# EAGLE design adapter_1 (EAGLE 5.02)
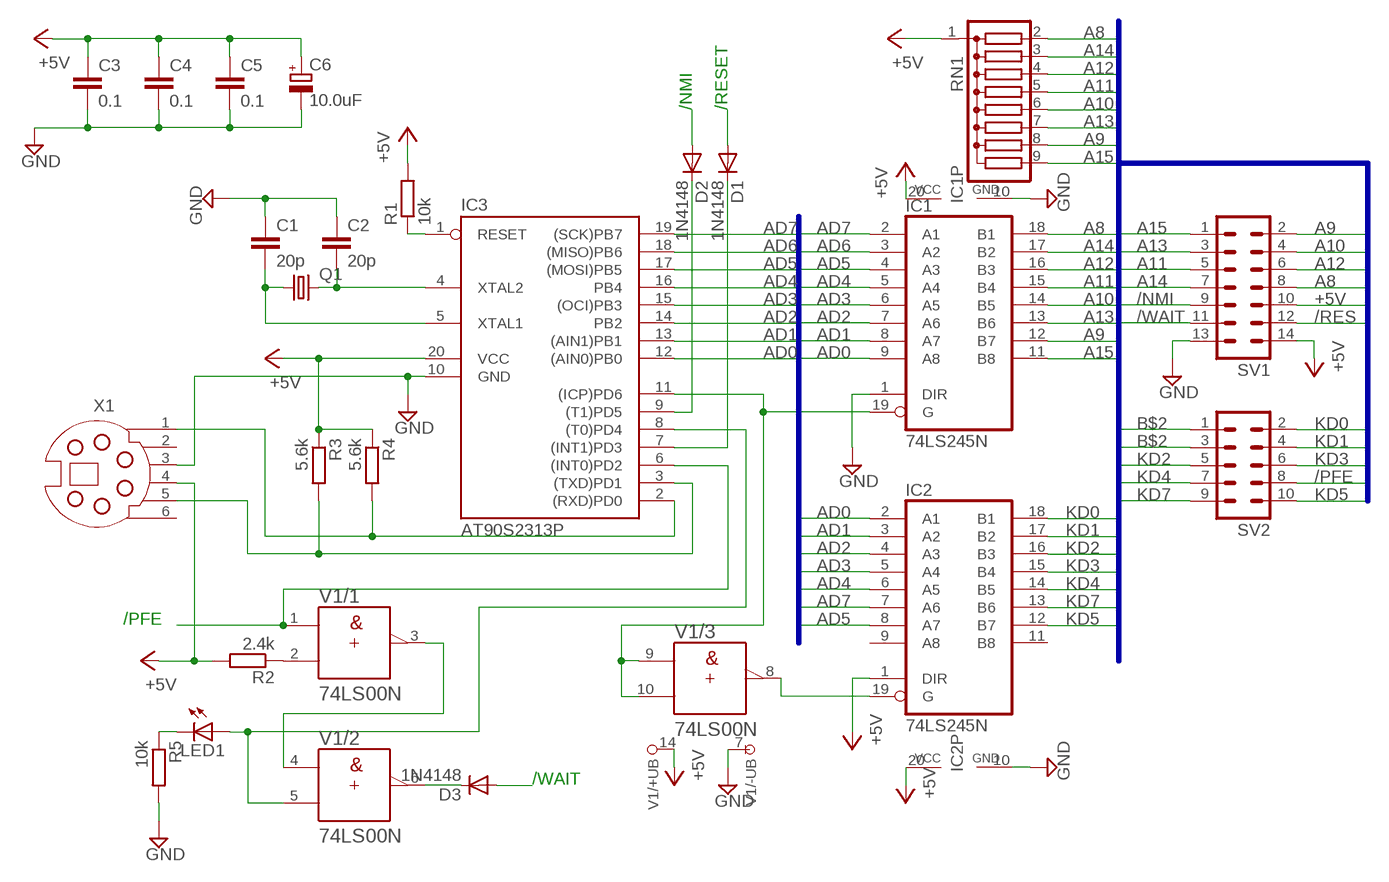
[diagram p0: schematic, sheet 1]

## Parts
C1  20p  C-EU050-024X044  [C050-024X044]
C2  20p  C-EU050-024X044  [C050-024X044]
C3  0.1  C-EU075-032X103  [C075-032X103]
C4  0.1  C-EU050-024X044  [C050-024X044]
C5  0.1  C-EU050-024X044  [C050-024X044]
C6  10.0uF  CPOL-EUE2-4  [E2-4]
D1  1N4148  [DO35-10]
D2  1N4148  [DO35-10]
D3  1N4148  [DO35-10]
IC1  74LS245N  [DIL20]
IC2  74LS245N  [DIL20]
IC3  AT90S2313P  [DIL20]
LED1  LED3MM  [LED3MM]
Q1  CRYSTALHC49U-V  [HC49U-V]
R1  10k  R-EU_0204/7  [0204/7]
R2  2.4k  R-EU_0204/7  [0204/7]
R3  5.6k  R-EU_0204/2V  [0204V]
R4  5.6k  R-EU_0204/2V  [0204V]
R5  10k  R-EU_0204/2V  [0204V]
RN1  G08R  [SIL9]
SV1  ML14  [ML14]
SV2  ML10  [ML10]
V1  74LS00N  [DIL14]
X1  SSV-G06  [SSV-BC06]

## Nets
+5V: C3.1 C4.1 C5.1 C6.+ IC1.20(VCC) IC2.1(DIR) IC2.20(VCC) IC3.20(VCC) R1.2 R2.2 R3.1 R4.1 RN1.1 SV1.10 SV1.14 V1.14(/+UB:+UB) X1.4
/NMI: D2.A SV1.9
/PFE: IC3.6((INT0)PD2) SV2.8 V1.1(/1:A)
/RES: D1.A SV1.12
/WAIT: D3.A SV1.11
A8: IC1.18(B1) RN1.2 SV1.8
A9: IC1.12(B7) RN1.8 SV1.2
A10: IC1.14(B5) RN1.6 SV1.4
A11: IC1.15(B4) RN1.5 SV1.5
A12: IC1.16(B3) RN1.4 SV1.6
A13: IC1.13(B6) RN1.7 SV1.3
A14: IC1.17(B2) RN1.3 SV1.7
A15: IC1.11(B8) RN1.9 SV1.1
AD0: IC1.9(A8) IC2.2(A1) IC3.12((AIN0)PB0)
AD1: IC1.8(A7) IC2.3(A2) IC3.13((AIN1)PB1)
AD2: IC1.7(A6) IC2.4(A3) IC3.14(PB2)
AD3: IC1.6(A5) IC2.5(A4) IC3.15((OCI)PB3)
AD4: IC1.5(A4) IC2.6(A5) IC3.16(PB4)
AD5: IC1.4(A3) IC2.8(A7) IC3.17((MOSI)PB5)
AD6: IC1.3(A2) IC3.18((MISO)PB6)
AD7: IC1.2(A1) IC2.7(A6) IC3.19((SCK)PB7)
B$2: SV2.1 SV2.3
GND: C1.1 C2.1 C3.2 C4.2 C5.2 C6.- IC1.1(DIR) IC1.10(GND) IC2.10(GND) IC3.10(GND) R5.2 SV1.13 V1.7(/-UB:-UB) X1.3
KD0: IC2.18(B1) SV2.2
KD1: IC2.17(B2) SV2.4
KD2: IC2.16(B3) SV2.5
KD3: IC2.15(B4) SV2.6
KD4: IC2.14(B5) SV2.7
KD5: IC2.12(B7) SV2.10
KD7: IC2.13(B6) SV2.9
N$1: IC3.1(RESET) R1.1
N$2: V1.3(/1:Y) V1.4(/2:A)
N$3: C2.2 IC3.4(XTAL2) Q1.2
N$4: C1.2 IC3.5(XTAL1) Q1.1
N$5: IC3.8((T0)PD4) LED1.A V1.5(/2:B)
N$6: IC1.19(G) IC3.11((ICP)PD6) V1.9(/3:A) V1.10(/3:B)
N$7: R2.1 V1.2(/1:B)
N$8: IC2.19(G) V1.8(/3:Y)
N$9: IC3.2((RXD)PD0) R4.2 X1.1
N$10: IC3.3((TXD)PD1) R3.2 X1.5
N$11: LED1.K(C) R5.1
N$13: D2.C IC3.9((T1)PD5)
N$14: D1.C IC3.7((INT1)PD3)
N$17: D3.C V1.6(/2:Y)
Unconnected: IC2.9(A8) IC2.11(B8) V1.11(/4:Y) V1.12(/4:A) V1.13(/4:B) X1.2 X1.6

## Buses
B$1
B$2

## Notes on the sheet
- /NMI | /RESET
- /PFE
- /WAIT

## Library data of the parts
C1-C5 = rcl:C-EU: CAPACITOR, European symbol
C6 = rcl:CPOL-EU: POLARIZED CAPACITOR, European symbol
D1-D3 = diode:1N4148: DIODE
IC1 IC2 = 74xx-eu:74*245: Octal BUS TRANSCEIVER, 3-state
IC3 = atmel:AT90S2313: MICROCONTROLLER 2 Kbytes FLASH 128 bytes SRAM 128 bytes EEPROM UART
LED1 = led:LED: LED
Q1 = crystal:CRYSTAL: CRYSTAL
R1-R5 = rcl:R-EU_: RESISTOR, European symbol
RN1 = resistor-sil:G08R: SIL RESISTOR
SV1 = con-ml:ML14: HARTING
SV2 = con-ml:ML10: HARTING
V1 = 74ttl-din:74*00: Quad 2-input NAND gate
X1 = con-yamaichi:SSV-G06: YAMAICHI CONNECTOR

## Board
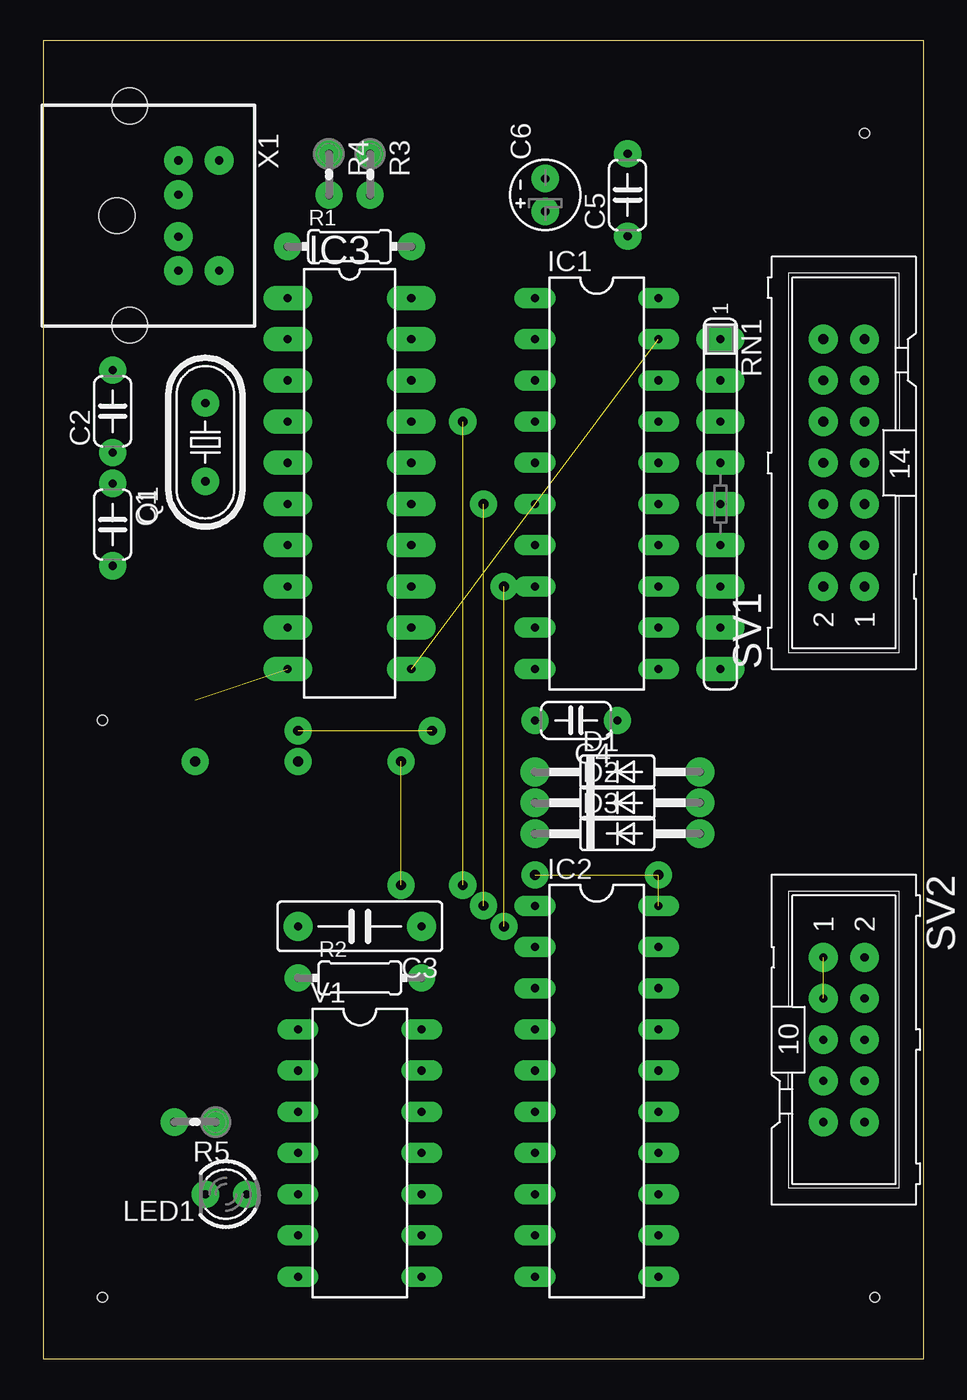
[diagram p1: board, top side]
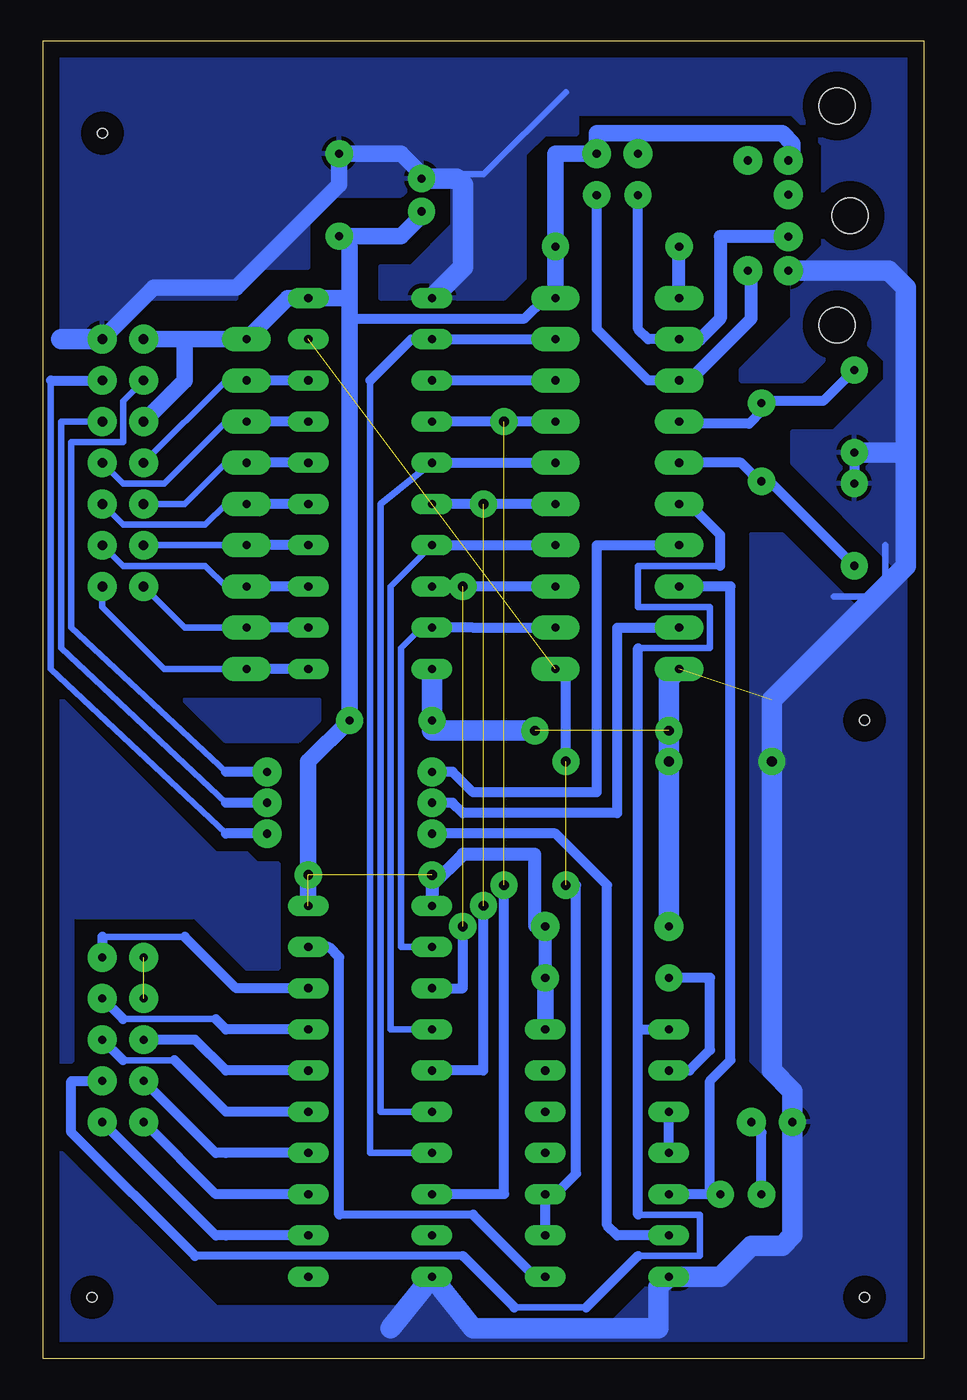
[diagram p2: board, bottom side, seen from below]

Size 54.28 x 81.27 mm. Coordinates in mm from the lower left corner, seen from the top.
Outline: 0,0 54.28,0 54.28,81.27 0,81.27 0,0
Copper layers (1*16): Top 0.035mm / dielectric 1.5mm / Bottom 0.035mm
Design rules "default": minimum track width 10mil, minimum drill 24mil, track to track 8mil, track to pad 8mil, pad to pad 8mil, via to via 8mil, smd to smd 8mil, copper to edge 40mil, drill to drill 8mil, minimum pad ring 10mil, minimum via ring 8mil, stop-mask expansion 4mil, vias tented up to drill 0mil, thermal gap 10mil
Holes 0.6 mm at 50.63,75.56 3.64,3.8 3.64,39.37 51.27,3.8

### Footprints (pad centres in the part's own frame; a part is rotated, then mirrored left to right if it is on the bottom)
C050-024X044 = drill 0.5 pad 1.676 round: 1 -2.54,0; 2 2.54,0
C075-032X103 = drill 0.5 pad 1.778 round: 1 -3.81,0; 2 3.81,0
E2-4 = drill 0.5 pad 1.676 round: + -1.016,0; - 1.016,0
DO35-10 = drill 0.5 pad 1.778 round: A 5.08,0; C -5.08,0
DIL20 = drill 0.5 pad 1.27 long: 1 -11.43,-3.81; 2 -8.89,-3.81; 3 -6.35,-3.81; 4 -3.81,-3.81; 5 -1.27,-3.81; 6 1.27,-3.81; 7 3.81,-3.81; 8 6.35,-3.81; 9 8.89,-3.81; 10 11.43,-3.81; 11 11.43,3.81; 12 8.89,3.81; 13 6.35,3.81; 14 3.81,3.81; 15 1.27,3.81; 16 -1.27,3.81; 17 -3.81,3.81; 18 -6.35,3.81; 19 -8.89,3.81; 20 -11.43,3.81
DIL20' = drill 0.5 pad 1.5 long: 1 -11.43,-3.81; 2 -8.89,-3.81; 3 -6.35,-3.81; 4 -3.81,-3.81; 5 -1.27,-3.81; 6 1.27,-3.81; 7 3.81,-3.81; 8 6.35,-3.81; 9 8.89,-3.81; 10 11.43,-3.81; 11 11.43,3.81; 12 8.89,3.81; 13 6.35,3.81; 14 3.81,3.81; 15 1.27,3.81; 16 -1.27,3.81; 17 -3.81,3.81; 18 -6.35,3.81; 19 -8.89,3.81; 20 -11.43,3.81
LED3MM = drill 0.5 pad 1.676 round: A -1.27,0; K 1.27,0
HC49U-V = drill 0.5 pad 1.676 round: 1 -2.413,0; 2 2.413,0
0204/7 = drill 0.5 pad 1.676 round: 1 -3.81,0; 2 3.81,0
0204V = drill 0.5 pad 1.778 round: 1 -1.27,0 | drill 0.5 pad 1.676 round: 2 1.27,0
SIL9 = drill 0.5 pad 1.5 long: 1 -10.16,0; 2 -7.62,0; 3 -5.08,0; 4 -2.54,0; 5 0,0; 6 2.54,0; 7 5.08,0; 8 7.62,0; 9 10.16,0
ML14 = drill 0.6 pad 1.778 round: 1 -7.62,-1.27; 2 -7.62,1.27; 3 -5.08,-1.27; 4 -5.08,1.27; 5 -2.54,-1.27; 6 -2.54,1.27; 7 0,-1.27; 8 0,1.27; 9 2.54,-1.27; 10 2.54,1.27; 11 5.08,-1.27; 12 5.08,1.27; 13 7.62,-1.27; 14 7.62,1.27
ML10 = drill 0.5 pad 1.778 round: 1 -5.08,-1.27; 2 -5.08,1.27; 3 -2.54,-1.27; 4 -2.54,1.27; 5 0,-1.27; 6 0,1.27; 7 2.54,-1.27; 8 2.54,1.27; 9 5.08,-1.27; 10 5.08,1.27
DIL14 = drill 0.5 pad 1.27 long: 1 -7.62,-3.81; 2 -5.08,-3.81; 3 -2.54,-3.81; 4 0,-3.81; 5 2.54,-3.81; 6 5.08,-3.81; 7 7.62,-3.81; 8 7.62,3.81; 9 5.08,3.81; 10 2.54,3.81; 11 0,3.81; 12 -2.54,3.81; 13 -5.08,3.81; 14 -7.62,3.81
SSV-BC06 = drill 0.5 pad 1.778 round: 1 1.3,8.5; 2 -1.3,8.5; 3 3.4,8.5; 4 -3.4,8.5; 5 3.4,11; 6 -3.4,11 | hole 2.2: -6.75,5.5; 0,4.7; 6.75,5.5

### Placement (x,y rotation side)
C1  4.28,51.43 270 top
C2  4.28,58.41 90 top
C3  19.52,26.66 180 top
C4  32.85,39.37 180 top
C5  36.03,71.75 90 top
C6  30.95,71.75 90 top
D1  35.39,36.19 0 top
D2  35.39,34.29 0 top
D3  35.39,32.38 0 top
IC1  34.12,53.97 270 top
IC2  34.12,16.5 270 top
IC3  AT90S2313P  [DIL20']  18.88,53.97 270 top
LED1  11.27,10.16 180 top
Q1  10,56.51 90 top
R1  18.88,68.57 0 top
R2  19.52,23.49 0 top
R3  20.15,73.02 270 top
R4  17.61,73.02 270 top
R5  9.36,14.6 180 top
RN1  41.74,52.7 270 top
SV1  49.37,55.24 90 top
SV2  49.37,19.68 270 top
V1  19.52,12.7 270 top
X1  -0.17,70.48 270 top

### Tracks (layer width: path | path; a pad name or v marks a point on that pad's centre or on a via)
+5V  (via drill 0.6 pad 1.68)  (2 unrouted)
  Bottom 0.61: IC3.20 23.33,65.4 24.6,64.13 35.39,64.13
  Bottom 0.813: V1.14 C3.1 23.96,26.66 23.96,31.11 28.41,31.11 30.31,29.2 | 30.31,29.2 IC2.1 | 30.31,29.2 v30.31,29.84
  Bottom 1.016: 45.55,62.86 RN1.1 39.2,65.4 IC1.20 35.39,65.4 | 45.55,62.86 SV1.14 | SV1.10 45.55,60.32 45.55,62.86 | IC2.20 37.94,36.83 C4.1 35.39,64.13 35.39,65.4 | IC3.20 R1.2 22.7,74.29 R3.1 20.15,75.56 17.61,75.56 | X1.4 8.31,73.88 8.09,73.66 8.09,74.92 8.73,75.56 17.61,75.56 | 17.61,75.56 R4.1 | V1.14 R2.2 | 35.39,65.4 35.39,68.57 C5.1 32.22,69.21 30.95,70.48 C6.+
  other vias: 37.94,29.84
/NMI
  Bottom 0.406: 43.02,34.29 53.17,43.81 53.17,57.78 SV1.9
  Bottom 0.61: D2.A 43.02,34.29
/PFE
  Bottom 0.406: 20.79,3.17 25.23,3.17 | 17.61,43.81 13.17,43.81 13.17,46.35 17.61,46.35 17.61,48.89 12.54,48.89 | 17.61,8.89 13.81,8.89 13.81,6.34 17.61,6.34
  Bottom 0.5: 28.41,6.34 44.92,6.34
  Bottom 0.61: 25.23,3.17 28.41,6.34 | IC3.6 14.44,52.7 12.54,50.8 12.54,48.89 | 17.61,20.31 17.61,43.81 | 17.61,20.31 V1.1 | 17.61,8.89 17.61,20.31 | 17.61,6.34 20.79,3.17 | 44.92,6.34 52.54,13.97 52.54,17.14 SV2.8
/RES
  Bottom 0.406: 43.02,36.19 52.54,45.08 52.54,56.51 49.37,56.51 49.37,59.05 SV1.12
  Bottom 0.61: D1.A 43.02,36.19
/WAIT
  Bottom 0.406: 43.02,32.38 53.81,42.54 53.81,60.32
  Bottom 0.61: D3.A 43.02,32.38 | 53.81,60.32 SV1.11
A8
  Bottom 0.406: SV1.8 43.02,60.32 RN1.2
  Bottom 0.61: IC1.18 RN1.2
A9
  Bottom 0.406: RN1.8 45.55,45.08 SV1.2
  Bottom 0.61: IC1.12 RN1.8
A10
  Bottom 0.406: RN1.6 SV1.4
  Bottom 0.61: IC1.14 RN1.6
A11
  Bottom 0.406: SV1.5 49.37,51.43 44.28,51.43 43.02,52.7 RN1.5
  Bottom 0.61: IC1.15 RN1.5
A12
  Bottom 0.406: SV1.6 45.55,52.7 43.02,55.24 RN1.4
  Bottom 0.61: IC1.16 RN1.4
A13
  Bottom 0.406: SV1.3 49.37,48.89 44.28,48.89 43.02,47.62 RN1.7
  Bottom 0.61: IC1.13 RN1.7
A14
  Bottom 0.406: SV1.7 49.37,53.97 46.82,53.97 43.02,57.78 RN1.3
  Bottom 0.61: IC1.17 RN1.3
A15
  Bottom 0.406: RN1.9 46.82,42.54 50.63,46.35 SV1.1
  Bottom 0.61: IC1.11 RN1.9
AD0
  Bottom 0.406: 27.77,45.08 30.95,45.08 32.22,43.81 32.22,25.39 IC2.2
  Bottom 0.61: IC3.12 27.77,45.08 IC1.9
AD1  (via drill 0.6 pad 1.68)  (1 unrouted)
  Bottom 0.61: IC3.13 v28.41,47.62 IC1.8 | v28.41,26.66 28.41,22.86 IC2.3
AD2
  Bottom 0.406: IC1.7 32.85,47.62 32.85,20.31 IC2.4
  Bottom 0.61: IC1.7 IC3.14
AD3  (via drill 0.6 pad 1.68)  (1 unrouted)
  Bottom 0.61: IC3.15 v27.14,52.7 IC1.6 | IC2.5 27.14,17.77 v27.14,27.93
AD4
  Bottom 0.406: IC2.6 33.49,15.24 33.49,52.7 IC1.5
  Bottom 0.61: IC1.5 IC3.16
AD5  (via drill 0.6 pad 1.68)  (1 unrouted)
  Bottom 0.61: IC3.17 v25.87,57.78 IC1.4 | IC2.8 25.87,10.16 v25.87,29.2
AD6
  Bottom 0.61: IC3.18 IC1.3
AD7
  Bottom 0.406: 34.12,60.32 34.12,12.7 IC2.7
  Bottom 0.61: IC3.19 IC1.2 31.58,62.86 34.12,60.32
B$2  (1 unrouted)
GND  (via drill 0.6 pad 1.68)  (2 unrouted)
  Bottom 0.406: 30.95,73.02 27.14,73.02 22.06,78.1 | 5.55,46.98 2.38,46.98 2.38,50.16
  Bottom 0.61: C2.1 C1.1
  Bottom 1.016: C6.- 30.95,73.02 32.22,74.29 C5.2 36.03,72.38 42.38,66.03 47.46,66.03 SV1.13
  Bottom 1.27: C3.2 v15.71,36.83 v15.71,38.73 15.71,41.91 IC3.10 | C4.2 IC1.10 30.31,38.73 v23.96,38.73 | C6.- 28.79,72.77 28.41,72.38 28.41,67.3 IC1.1 | X1.3 2.15,67.08 1.1,66.03 1.1,55.88 | 1.1,55.88 C2.1 | 9.36,40.64 v9.36,36.83 | 9.36,40.64 1.1,48.89 1.1,55.88 | 9.36,40.64 9.36,17.77 8.09,16.5 R5.2 8.09,7.62 8.73,6.98 10.63,6.98 12.54,5.08 V1.7 16.34,4.44 16.34,1.9 27.77,1.9 IC2.10 32.85,1.9 | SV1.13 53.17,62.86
  pour Bottom: 8.09,16.5 0.47,16.5 0.47,-0.01 54.45,-0.01 54.45,30.47 39.84,30.47 39.84,24.12 41.74,24.12 44.92,27.3 52.54,27.3 52.54,18.41 53.81,18.41 53.81,13.33 43.65,3.17 32.22,3.17 30.31,5.08 27.14,1.9 19.52,1.9 16.34,5.08 13.17,5.08 12.54,5.71 11.9,5.71 10.63,6.98 8.73,6.98 8.09,7.62
  pour Bottom: 54.45,62.86 50.63,62.86 48.09,65.4 42.38,65.4 42.38,66.67 41.74,66.67 41.11,67.3 37.94,67.3 37.94,70.48 36.66,71.75 32.22,71.75 31.58,72.38 29.04,72.38 29.04,69.84 31.58,67.3 33.49,67.3 33.49,65.4 25.87,65.4 24.6,66.67 24.6,74.29 23.33,75.56 23.33,80.64 54.45,80.64
  pour Bottom: 0.47,16.5 -0.17,79.37 10.63,79.37 6.18,75.56 6.18,68.57 8.09,66.67 8.09,64.13 11.27,60.96 11.27,60.32 7.46,60.32 4.92,62.86 3.64,62.86 2.38,61.59 2.38,60.32 5.55,57.15 8.09,57.15 8.09,55.24 1.74,48.89 4.28,46.35 8.73,50.8 10.63,50.8 10.63,18.41 8.73,16.5
  pour Bottom: 0.47,74.92 0.47,80.64 23.33,80.64 23.33,75.56 21.42,75.56 21.42,76.83 8.09,76.83 6.18,74.92
KD0
  Bottom 0.406: 45.55,26.03 50.63,26.03
  Bottom 0.61: IC2.18 42.38,22.86 45.55,26.03 | 50.63,26.03 SV2.2
KD1
  Bottom 0.406: 43.65,20.95 49.37,20.95
  Bottom 0.61: IC2.17 43.02,20.31 43.65,20.95 | 49.37,20.95 SV2.4
KD2
  Bottom 0.61: IC2.16 43.02,17.77 44.92,19.68 SV2.5
KD3
  Bottom 0.406: 46.19,18.41 49.37,18.41
  Bottom 0.61: IC2.15 43.02,15.24 46.19,18.41 | 49.37,18.41 SV2.6
KD4
  Bottom 0.61: IC2.14 43.02,12.7 43.65,12.7 SV2.7
KD5
  Bottom 0.61: IC2.12 43.02,7.62 43.65,7.62 SV2.10
KD7
  Bottom 0.61: IC2.13 43.02,10.16 43.65,10.16 SV2.9
N$1
  Bottom 0.813: IC3.1 R1.1
N$2
  Bottom 0.61: V1.4 V1.3
N$3
  Bottom 0.61: IC3.4 14.95,57.65 10.76,57.65 10,58.41 Q1.2 10,59.05 6.18,59.05 C2.2
N$4
  Bottom 0.61: IC3.5 11.27,55.24 10,53.97 Q1.1 10,54.61 C1.2
N$5
  Bottom 0.61: LED1.A 13.17,10.16 | 13.17,10.16 V1.5 | 13.17,10.16 13.17,17.14 11.9,18.41 11.9,47.62 IC3.8
N$6  (via drill 0.6 pad 1.68)  (2 unrouted)
  Bottom 0.61: V1.9 V1.10 22.7,10.16 21.42,11.43 21.42,29.2 v22.06,29.2 | IC3.11 22.06,41.91 22.06,36.83
N$7
  Bottom 0.61: R2.1 13.17,23.49 13.17,19.04 14.44,17.77 V1.2
N$8
  Bottom 0.5: 27.77,8.89 36.03,8.89
  Bottom 0.61: IC2.19 36.66,25.39 36.03,24.76 36.03,8.89 | 27.77,8.89 23.96,5.08 V1.8
N$9
  Bottom 0.61: R4.2 17.61,63.5 16.98,62.86 IC3.2
  Bottom 0.813: IC3.2 13.81,62.86 12.54,64.13 12.54,69.21 12.51,69.18 X1.1
N$10
  Bottom 0.61: R3.2 20.15,63.5 16.98,60.32 IC3.3
  Bottom 0.813: IC3.3 14.44,60.32 10.63,64.13 10.63,67.3 10.84,67.1 X1.5
N$11
  Bottom 0.61: LED1.K 10,13.97 R5.1
N$12  (via drill 0.6 pad 1.68)
  other vias: 22.06,36.83
N$13
  Bottom 0.61: IC3.9 18.88,45.08 18.88,33.65 28.41,33.65 29.04,34.29 D2.C
N$14
  Bottom 0.61: IC3.7 20.15,50.16 20.15,34.92 27.77,34.92 29.04,36.19 D1.C
N$15
  pour Bottom: 37.3,40.64 37.3,40 37.3,39.37 38.57,38.1 43.02,38.1 45.55,40.64
N$16
  pour Bottom: 39.84,30.47 39.84,24.12 41.74,24.12 44.92,27.3 52.54,27.3 52.54,18.41 53.81,18.41 53.81,40.64 53.81,41.27 43.65,31.11 41.74,31.11 41.11,30.47
N$17
  Bottom 0.61: V1.6 18.88,7.62 19.52,8.25 19.52,29.2 22.7,32.38 D3.C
